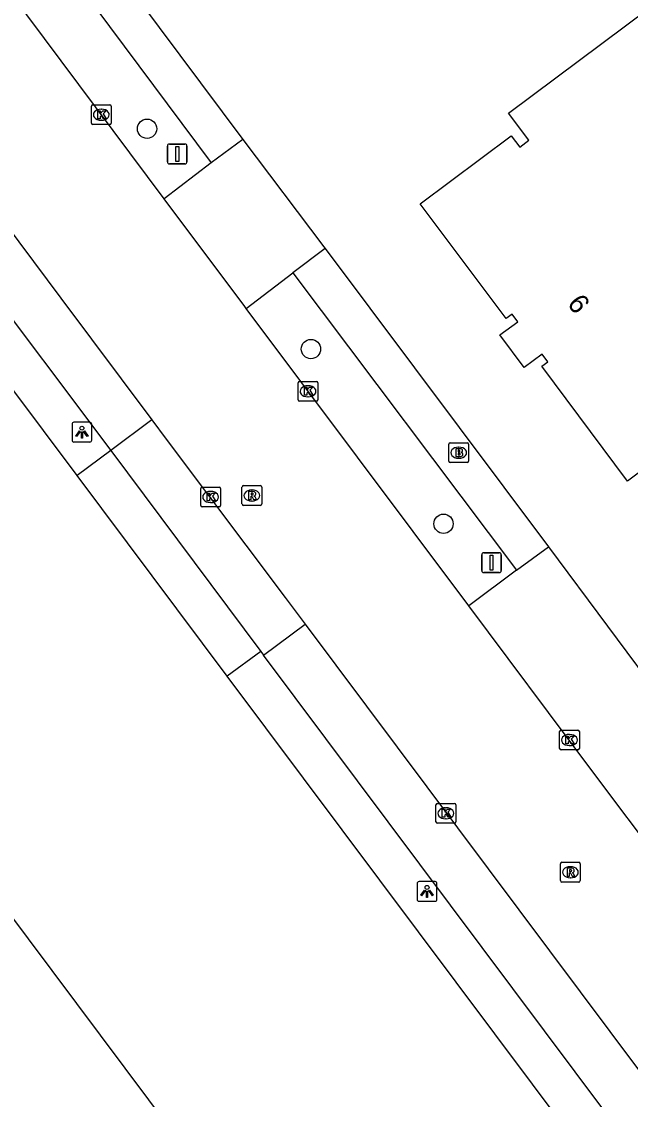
# Model space of a CAD drawing. Extents: x 156651 to 158072, y 387631 to 388990.
# Drawn here: x 157731.8 to 157762.6, y 388530.3 to 388584.8 of the extents above; entities that cross this region are included whole.
import ezdxf

# ---------------------------------------------------------------- set-up
doc = ezdxf.new("R2010")
doc.units = 0
for name, color, linetype in [('IMGEO_Boom', 7, 'Continuous'), ('IMGEO_Brandkraan', 7, 'Continuous'), ('IMGEO_Kolk', 7, 'Continuous'), ('IMGEO_Lichtpunt', 7, 'Continuous'), ('IMGEO_Pand', 7, 'Continuous'), ('IMGEO_Pand_nummerreeks', 7, 'Continuous'), ('IMGEO_Parkeervlak_open', 7, 'Continuous'), ('IMGEO_Rijbaan_lokaal_gesloten', 7, 'Continuous'), ('IMGEO_Rioolput', 7, 'Continuous'), ('IMGEO_Verkeersbordpaal', 7, 'Continuous'), ('IMGEO_Voetpad_open', 7, 'Continuous')]:
    doc.layers.add(name, color=color, linetype=linetype)

msp = doc.modelspace()

# ---------------------------------------------------------------- linework, layer by layer
at = {"layer": 'IMGEO_Boom'}
for centre in [(157738.13, 388579.359), (157746.416, 388568.217), (157753.12, 388559.377)]:
    msp.add_circle(centre, 0.489, dxfattribs=at)
at = {"layer": 'IMGEO_Brandkraan'}
for p, q in [((157753.387, 388562.548), (157753.387, 388563.4)), ((157753.462, 388563.474), (157754.314, 388563.474)), ((157753.875, 388563.254), (157753.9, 388563.254)), ((157754.388, 388563.4), (157754.388, 388562.548)), ((157753.898, 388562.694), (157753.873, 388562.694)), ((157754.314, 388562.474), (157753.462, 388562.474))]:
    msp.add_line(p, q, dxfattribs=at)
for points in [[(157753.387, 388562.548), (157753.387, 388563.4)], [(157753.462, 388563.474), (157754.314, 388563.474)], [(157754.388, 388563.4), (157754.388, 388562.548)], [(157753.735, 388563.174), (157753.735, 388562.774), (157753.948, 388562.774)], [(157753.966, 388563.174), (157753.735, 388563.174)], [(157753.914, 388563.093), (157753.86, 388563.093), (157753.86, 388563.017)], [(157753.86, 388563.017), (157753.913, 388563.017)], [(157753.922, 388562.941), (157753.86, 388562.941), (157753.86, 388562.86)], [(157753.86, 388562.86), (157753.922, 388562.86)], [(157754.314, 388562.474), (157753.462, 388562.474)]]:
    msp.add_lwpolyline(points, dxfattribs=at)
for centre, radius, start, end in [((157753.464, 388563.398), 0.0765, 91.552, 178.448), ((157753.464, 388563.398), 0.0765, 91.552, 178.448), ((157754.312, 388563.398), 0.0765, 1.552, 88.448), ((157754.312, 388563.398), 0.0765, 1.552, 88.448), ((157753.915, 388563.055), 0.0379, 267.8285, 90.9355), ((157753.923, 388562.9), 0.0404, 269.8759, 90.5077), ((157753.954, 388563.025), 0.251, 268.6676, 293.5347), ((157753.97, 388563.029), 0.145, 59.4692, 91.5367), ((157753.995, 388563.076), 0.0922, 285.5137, 58.1501), ((157754, 388562.884), 0.105, 301.3115, 78.989), ((157753.464, 388562.55), 0.0765, 181.552, 268.448), ((157753.464, 388562.55), 0.0765, 181.552, 268.448), ((157754.312, 388562.55), 0.0765, 271.552, 358.448), ((157754.312, 388562.55), 0.0765, 271.552, 358.448)]:
    msp.add_arc(centre, radius, start, end, dxfattribs=at)
for centre, major_axis, ratio, start_param, end_param in [((157753.874, 388562.974), (-0.387, 0.002), 0.722429, 4.712389, 7.853982), ((157753.899, 388562.974), (-0.39, 0.002), 0.717154, 1.570796, 4.712389)]:
    msp.add_ellipse(centre, major_axis=major_axis, ratio=ratio, start_param=start_param, end_param=end_param, dxfattribs=at)
at = {"layer": 'IMGEO_Kolk'}
for p, q in [((157735.316, 388579.642), (157735.316, 388580.494)), ((157735.391, 388580.568), (157736.243, 388580.568)), ((157735.804, 388580.348), (157735.829, 388580.348)), ((157736.317, 388580.494), (157736.317, 388579.642)), ((157735.827, 388579.788), (157735.802, 388579.788)), ((157736.243, 388579.568), (157735.391, 388579.568)), ((157745.767, 388565.654), (157745.767, 388566.506)), ((157745.842, 388566.58), (157746.694, 388566.58)), ((157746.768, 388566.506), (157746.768, 388565.654)), ((157746.255, 388566.36), (157746.28, 388566.36)), ((157746.694, 388565.58), (157745.842, 388565.58)), ((157746.278, 388565.8), (157746.253, 388565.8)), ((157740.843, 388560.307), (157740.843, 388561.159)), ((157740.918, 388561.233), (157741.77, 388561.233)), ((157741.844, 388561.159), (157741.844, 388560.307)), ((157741.331, 388561.013), (157741.356, 388561.013)), ((157741.77, 388560.233), (157740.918, 388560.233)), ((157741.354, 388560.453), (157741.329, 388560.453)), ((157758.987, 388548.015), (157758.987, 388548.867)), ((157759.062, 388548.941), (157759.914, 388548.941)), ((157759.475, 388548.721), (157759.5, 388548.721)), ((157759.988, 388548.867), (157759.988, 388548.015)), ((157759.498, 388548.161), (157759.473, 388548.161)), ((157759.914, 388547.941), (157759.062, 388547.941)), ((157752.814, 388545.234), (157753.666, 388545.234)), ((157752.739, 388544.308), (157752.739, 388545.16)), ((157753.227, 388545.014), (157753.252, 388545.014)), ((157753.74, 388545.16), (157753.74, 388544.308)), ((157753.666, 388544.234), (157752.814, 388544.234)), ((157753.25, 388544.454), (157753.225, 388544.454))]:
    msp.add_line(p, q, dxfattribs=at)
for points in [[(157735.316, 388579.642), (157735.316, 388580.494)], [(157735.391, 388580.568), (157736.243, 388580.568)], [(157735.637, 388580.268), (157735.76, 388580.268), (157735.76, 388580.117), (157735.89, 388580.268), (157736.054, 388580.268), (157735.908, 388580.117), (157736.061, 388579.868), (157735.909, 388579.868), (157735.824, 388580.032), (157735.76, 388579.965), (157735.76, 388579.868), (157735.637, 388579.868), (157735.637, 388580.268)], [(157736.317, 388580.494), (157736.317, 388579.642)], [(157736.243, 388579.568), (157735.391, 388579.568)], [(157745.767, 388565.654), (157745.767, 388566.506)], [(157745.842, 388566.58), (157746.694, 388566.58)], [(157746.768, 388566.506), (157746.768, 388565.654)], [(157746.088, 388566.28), (157746.211, 388566.28), (157746.211, 388566.129), (157746.341, 388566.28), (157746.505, 388566.28), (157746.359, 388566.129), (157746.512, 388565.88), (157746.36, 388565.88), (157746.275, 388566.044), (157746.211, 388565.977), (157746.211, 388565.88), (157746.088, 388565.88), (157746.088, 388566.28)], [(157746.694, 388565.58), (157745.842, 388565.58)], [(157740.843, 388560.307), (157740.843, 388561.159)], [(157740.918, 388561.233), (157741.77, 388561.233)], [(157741.844, 388561.159), (157741.844, 388560.307)], [(157741.164, 388560.933), (157741.287, 388560.933), (157741.287, 388560.782), (157741.417, 388560.933), (157741.581, 388560.933), (157741.435, 388560.782), (157741.588, 388560.533), (157741.436, 388560.533), (157741.351, 388560.697), (157741.287, 388560.63), (157741.287, 388560.533), (157741.164, 388560.533), (157741.164, 388560.933)], [(157741.77, 388560.233), (157740.918, 388560.233)], [(157758.987, 388548.015), (157758.987, 388548.867)], [(157759.062, 388548.941), (157759.914, 388548.941)], [(157759.308, 388548.641), (157759.431, 388548.641), (157759.431, 388548.49), (157759.561, 388548.641), (157759.725, 388548.641), (157759.579, 388548.49), (157759.732, 388548.241), (157759.58, 388548.241), (157759.495, 388548.405), (157759.431, 388548.338), (157759.431, 388548.241), (157759.308, 388548.241), (157759.308, 388548.641)], [(157759.988, 388548.867), (157759.988, 388548.015)], [(157759.914, 388547.941), (157759.062, 388547.941)], [(157752.814, 388545.234), (157753.666, 388545.234)], [(157752.739, 388544.308), (157752.739, 388545.16)], [(157753.06, 388544.934), (157753.183, 388544.934), (157753.183, 388544.783), (157753.313, 388544.934), (157753.477, 388544.934), (157753.331, 388544.783), (157753.484, 388544.534), (157753.332, 388544.534), (157753.247, 388544.698), (157753.183, 388544.631), (157753.183, 388544.534), (157753.06, 388544.534), (157753.06, 388544.934)], [(157753.74, 388545.16), (157753.74, 388544.308)], [(157753.666, 388544.234), (157752.814, 388544.234)]]:
    msp.add_lwpolyline(points, dxfattribs=at)
for centre, start, end in [((157735.393, 388580.492), 91.552, 178.448), ((157735.393, 388580.492), 91.552, 178.448), ((157736.241, 388580.492), 1.552, 88.448), ((157736.241, 388580.492), 1.552, 88.448), ((157735.393, 388579.644), 181.552, 268.448), ((157735.393, 388579.644), 181.552, 268.448), ((157736.241, 388579.644), 271.552, 358.448), ((157736.241, 388579.644), 271.552, 358.448), ((157745.844, 388566.504), 91.552, 178.448), ((157745.844, 388566.504), 91.552, 178.448), ((157746.692, 388566.504), 1.552, 88.448), ((157746.692, 388566.504), 1.552, 88.448), ((157745.844, 388565.656), 181.552, 268.448), ((157745.844, 388565.656), 181.552, 268.448), ((157746.692, 388565.656), 271.552, 358.448), ((157746.692, 388565.656), 271.552, 358.448), ((157740.92, 388561.157), 91.552, 178.448), ((157740.92, 388561.157), 91.552, 178.448), ((157741.768, 388561.157), 1.552, 88.448), ((157741.768, 388561.157), 1.552, 88.448), ((157740.92, 388560.309), 181.552, 268.448), ((157740.92, 388560.309), 181.552, 268.448), ((157741.768, 388560.309), 271.552, 358.448), ((157741.768, 388560.309), 271.552, 358.448), ((157759.064, 388548.865), 91.552, 178.448), ((157759.064, 388548.865), 91.552, 178.448), ((157759.912, 388548.865), 1.552, 88.448), ((157759.912, 388548.865), 1.552, 88.448), ((157759.064, 388548.017), 181.552, 268.448), ((157759.064, 388548.017), 181.552, 268.448), ((157759.912, 388548.017), 271.552, 358.448), ((157759.912, 388548.017), 271.552, 358.448), ((157752.816, 388545.158), 91.552, 178.448), ((157752.816, 388545.158), 91.552, 178.448), ((157753.664, 388545.158), 1.552, 88.448), ((157753.664, 388545.158), 1.552, 88.448), ((157752.816, 388544.31), 181.552, 268.448), ((157752.816, 388544.31), 181.552, 268.448), ((157753.664, 388544.31), 271.552, 358.448), ((157753.664, 388544.31), 271.552, 358.448)]:
    msp.add_arc(centre, 0.0765, start, end, dxfattribs=at)
for centre, major_axis, ratio, start_param, end_param in [((157735.803, 388580.068), (-0.387, 0.002), 0.722429, 4.712389, 7.853982), ((157735.828, 388580.068), (-0.39, 0.002), 0.717154, 1.570796, 4.712389), ((157746.254, 388566.08), (-0.387, 0.002), 0.722429, 4.712389, 7.853982), ((157746.279, 388566.08), (-0.39, 0.002), 0.717154, 1.570796, 4.712389), ((157741.33, 388560.733), (-0.387, 0.002), 0.722429, 4.712389, 7.853982), ((157741.355, 388560.733), (-0.39, 0.002), 0.717154, 1.570796, 4.712389), ((157759.474, 388548.441), (-0.387, 0.002), 0.722429, 4.712389, 7.853982), ((157759.499, 388548.441), (-0.39, 0.002), 0.717154, 1.570796, 4.712389), ((157753.226, 388544.734), (-0.387, 0.002), 0.722429, 4.712389, 7.853982), ((157753.251, 388544.734), (-0.39, 0.002), 0.717154, 1.570796, 4.712389)]:
    msp.add_ellipse(centre, major_axis=major_axis, ratio=ratio, start_param=start_param, end_param=end_param, dxfattribs=at)
at = {"layer": 'IMGEO_Lichtpunt'}
for p, q in [((157734.336, 388564.416), (157734.336, 388563.609)), ((157734.336, 388564.416), (157734.336, 388563.609)), ((157735.238, 388564.511), (157734.43, 388564.511)), ((157735.238, 388564.511), (157734.43, 388564.511)), ((157735.332, 388563.609), (157735.332, 388564.416)), ((157735.332, 388563.609), (157735.332, 388564.416)), ((157734.43, 388563.515), (157735.238, 388563.515)), ((157734.43, 388563.515), (157735.238, 388563.515)), ((157751.788, 388541.186), (157751.788, 388540.379)), ((157751.788, 388541.186), (157751.788, 388540.379)), ((157752.69, 388541.281), (157751.882, 388541.281)), ((157752.69, 388541.281), (157751.882, 388541.281)), ((157752.784, 388540.379), (157752.784, 388541.186)), ((157752.784, 388540.379), (157752.784, 388541.186)), ((157751.882, 388540.285), (157752.69, 388540.285)), ((157751.882, 388540.285), (157752.69, 388540.285))]:
    msp.add_line(p, q, dxfattribs=at)
for points in [[(157734.71, 388564.08), (157734.749, 388564.052), (157734.561, 388563.79), (157734.523, 388563.817), (157734.71, 388564.08)], [(157734.812, 388564.032), (157734.859, 388564.032), (157734.859, 388563.71), (157734.812, 388563.71), (157734.812, 388564.032)], [(157734.922, 388564.052), (157734.96, 388564.079), (157735.147, 388563.817), (157735.108, 388563.789), (157734.922, 388564.052)], [(157752.162, 388540.85), (157752.201, 388540.822), (157752.013, 388540.56), (157751.975, 388540.587), (157752.162, 388540.85)], [(157752.264, 388540.802), (157752.311, 388540.802), (157752.311, 388540.48), (157752.264, 388540.48), (157752.264, 388540.802)], [(157752.374, 388540.822), (157752.412, 388540.849), (157752.599, 388540.587), (157752.56, 388540.559), (157752.374, 388540.822)]]:
    msp.add_lwpolyline(points, dxfattribs=at)
for centre in [(157734.835, 388564.214), (157752.287, 388540.984)]:
    msp.add_circle(centre, 0.0994, dxfattribs=at)
for centre, start, end in [((157734.43, 388564.416), 90, 180), ((157734.43, 388564.416), 90, 180), ((157735.238, 388564.416), 0, 90), ((157735.238, 388564.416), 0, 90), ((157734.43, 388563.609), 180, 270), ((157734.43, 388563.609), 180, 270), ((157735.238, 388563.609), 270, 0), ((157735.238, 388563.609), 270, 360), ((157751.882, 388541.186), 90, 180), ((157751.882, 388541.186), 90, 180), ((157752.69, 388541.186), 0, 90), ((157752.69, 388541.186), 0, 90), ((157751.882, 388540.379), 180, 270), ((157751.882, 388540.379), 180, 270), ((157752.69, 388540.379), 270, 0), ((157752.69, 388540.379), 270, 360)]:
    msp.add_arc(centre, 0.0946, start, end, dxfattribs=at)
at = {"layer": 'IMGEO_Pand'}
for points in [[(157795.49, 388609.351), (157800.933, 388602.076), (157809.912, 388590.06), (157770.834, 388560.859), (157767.103, 388565.883), (157766.618, 388565.55), (157767.037, 388564.99), (157762.428, 388561.536), (157758.085, 388567.345), (157758.389, 388567.572), (157758.103, 388567.958), (157757.203, 388567.285), (157755.975, 388568.927), (157756.875, 388569.597), (157756.586, 388569.987), (157756.282, 388569.759), (157751.946, 388575.556), (157756.546, 388578.995), (157756.971, 388578.426), (157757.429, 388578.783), (157756.406, 388580.153), (157795.49, 388609.351)], [(157694.419, 388474.218), (157682.965, 388489.503), (157670.362, 388480.058), (157658.428, 388495.983), (157663.8, 388500), (157722.017, 388543.534), (157726.021, 388546.528), (157752.812, 388510.688), (157757.04, 388513.816), (157758.463, 388511.892), (157759.027, 388511.13), (157755.454, 388508.456), (157754.829, 388507.989), (157760.801, 388500), (157762.018, 388498.372), (157743.316, 388484.392), (157744.825, 388482.374)]]:
    msp.add_lwpolyline(points, dxfattribs=at)
at = {"layer": 'IMGEO_Parkeervlak_open'}
for points in [[(157738.371, 388564.633), (157736.304, 388563.087)], [(157744.014, 388552.734), (157746.116, 388554.3)]]:
    msp.add_lwpolyline(points, dxfattribs=at)
at = {"layer": 'IMGEO_Rijbaan_lokaal_gesloten'}
for points in [[(157677.044, 388646.782), (157678.366, 388644.971), (157691.031, 388628.022), (157702.886, 388612.138), (157715.525, 388595.248), (157733.77, 388570.785), (157738.371, 388564.633)], [(157739.001, 388575.812), (157729.45, 388588.589)], [(157743.149, 388570.269), (157743.08, 388570.36), (157739.001, 388575.812)], [(157754.398, 388555.23), (157743.149, 388570.269)], [(157738.371, 388564.633), (157739.101, 388563.658), (157745.11, 388555.645), (157746.116, 388554.3)], [(157764.445, 388541.799), (157760.423, 388547.176), (157754.398, 388555.23)], [(157746.116, 388554.3), (157786.233, 388500.645)]]:
    msp.add_lwpolyline(points, dxfattribs=at)
at = {"layer": 'IMGEO_Rioolput'}
for p, q in [((157742.93, 388560.382), (157742.93, 388561.234)), ((157743.005, 388561.308), (157743.857, 388561.308)), ((157743.418, 388561.088), (157743.443, 388561.088)), ((157743.931, 388561.234), (157743.931, 388560.382)), ((157743.441, 388560.528), (157743.416, 388560.528)), ((157743.857, 388560.308), (157743.005, 388560.308)), ((157759.034, 388541.327), (157759.034, 388542.179)), ((157759.109, 388542.253), (157759.961, 388542.253)), ((157759.522, 388542.033), (157759.547, 388542.033)), ((157760.035, 388542.179), (157760.035, 388541.327)), ((157759.545, 388541.473), (157759.52, 388541.473)), ((157759.961, 388541.253), (157759.109, 388541.253))]:
    msp.add_line(p, q, dxfattribs=at)
for points in [[(157742.93, 388560.382), (157742.93, 388561.234)], [(157743.005, 388561.308), (157743.857, 388561.308)], [(157743.931, 388561.234), (157743.931, 388560.382)], [(157743.519, 388561.006), (157743.267, 388561.008), (157743.267, 388560.608)], [(157743.267, 388560.608), (157743.391, 388560.608), (157743.391, 388560.77), (157743.402, 388560.77)], [(157743.445, 388560.927), (157743.391, 388560.927), (157743.391, 388560.846)], [(157743.391, 388560.846), (157743.443, 388560.846)], [(157743.449, 388560.741), (157743.52, 388560.608), (157743.66, 388560.608), (157743.595, 388560.734)], [(157743.857, 388560.308), (157743.005, 388560.308)], [(157759.034, 388541.327), (157759.034, 388542.179)], [(157759.109, 388542.253), (157759.961, 388542.253)], [(157760.035, 388542.179), (157760.035, 388541.327)], [(157759.623, 388541.951), (157759.371, 388541.953), (157759.371, 388541.553)], [(157759.371, 388541.553), (157759.495, 388541.553), (157759.495, 388541.715), (157759.506, 388541.715)], [(157759.549, 388541.872), (157759.495, 388541.872), (157759.495, 388541.791)], [(157759.495, 388541.791), (157759.547, 388541.791)], [(157759.553, 388541.686), (157759.624, 388541.553), (157759.764, 388541.553), (157759.699, 388541.679)], [(157759.961, 388541.253), (157759.109, 388541.253)]]:
    msp.add_lwpolyline(points, dxfattribs=at)
for centre, radius, start, end in [((157743.007, 388561.232), 0.0765, 91.552, 178.448), ((157743.007, 388561.232), 0.0765, 91.552, 178.448), ((157743.855, 388561.232), 0.0765, 1.552, 88.448), ((157743.855, 388561.232), 0.0765, 1.552, 88.448), ((157743.401, 388560.717), 0.0533, 26.0293, 88.6989), ((157743.427, 388561.035), 0.19, 274.7715, 282.9687), ((157743.451, 388560.831), 0.0964, 77.0061, 93.1865), ((157743.465, 388560.888), 0.0378, 276.6634, 79.6772), ((157743.518, 388560.896), 0.109, 350.3612, 89.416), ((157743.516, 388560.896), 0.112, 277.5842, 350.9817), ((157743.5, 388560.681), 0.108, 29.5134, 73.7905), ((157743.007, 388560.384), 0.0765, 181.552, 268.448), ((157743.007, 388560.384), 0.0765, 181.552, 268.448), ((157743.855, 388560.384), 0.0765, 271.552, 358.448), ((157743.855, 388560.384), 0.0765, 271.552, 358.448), ((157759.111, 388542.177), 0.0765, 91.552, 178.448), ((157759.111, 388542.177), 0.0765, 91.552, 178.448), ((157759.959, 388542.177), 0.0765, 1.552, 88.448), ((157759.959, 388542.177), 0.0765, 1.552, 88.448), ((157759.505, 388541.662), 0.0533, 26.0293, 88.6989), ((157759.531, 388541.98), 0.19, 274.7715, 282.9687), ((157759.555, 388541.776), 0.0964, 77.0061, 93.1865), ((157759.569, 388541.833), 0.0378, 276.6634, 79.6772), ((157759.622, 388541.841), 0.109, 350.3612, 89.416), ((157759.62, 388541.841), 0.112, 277.5842, 350.9817), ((157759.604, 388541.626), 0.108, 29.5134, 73.7905), ((157759.111, 388541.329), 0.0765, 181.552, 268.448), ((157759.111, 388541.329), 0.0765, 181.552, 268.448), ((157759.959, 388541.329), 0.0765, 271.552, 358.448), ((157759.959, 388541.329), 0.0765, 271.552, 358.448)]:
    msp.add_arc(centre, radius, start, end, dxfattribs=at)
for centre, major_axis, ratio, start_param, end_param in [((157743.417, 388560.808), (-0.387, 0.002), 0.722429, 4.712389, 7.853982), ((157743.442, 388560.808), (-0.39, 0.002), 0.717154, 1.570796, 4.712389), ((157759.521, 388541.753), (-0.387, 0.002), 0.722429, 4.712389, 7.853982), ((157759.546, 388541.753), (-0.39, 0.002), 0.717154, 1.570796, 4.712389)]:
    msp.add_ellipse(centre, major_axis=major_axis, ratio=ratio, start_param=start_param, end_param=end_param, dxfattribs=at)
at = {"layer": 'IMGEO_Verkeersbordpaal'}
for p, q in [((157739.258, 388578.585), (157740.048, 388578.585)), ((157740.048, 388578.585), (157739.258, 388578.585)), ((157739.158, 388577.685), (157739.158, 388578.485)), ((157739.158, 388578.485), (157739.158, 388577.685)), ((157740.148, 388578.485), (157740.148, 388577.685)), ((157740.148, 388577.685), (157740.148, 388578.485)), ((157740.048, 388577.585), (157739.258, 388577.585)), ((157739.258, 388577.585), (157740.048, 388577.585)), ((157755.051, 388557.01), (157755.051, 388557.81)), ((157755.051, 388557.81), (157755.051, 388557.01)), ((157755.151, 388557.91), (157755.941, 388557.91)), ((157755.941, 388557.91), (157755.151, 388557.91)), ((157756.041, 388557.81), (157756.041, 388557.01)), ((157756.041, 388557.01), (157756.041, 388557.81)), ((157755.941, 388556.91), (157755.151, 388556.91)), ((157755.151, 388556.91), (157755.941, 388556.91))]:
    msp.add_line(p, q, dxfattribs=at)
for points in [[(157739.578, 388578.46), (157739.728, 388578.46), (157739.728, 388577.71), (157739.578, 388577.71), (157739.578, 388578.46)], [(157755.471, 388557.785), (157755.621, 388557.785), (157755.621, 388557.035), (157755.471, 388557.035), (157755.471, 388557.785)]]:
    msp.add_lwpolyline(points, dxfattribs=at)
for centre, start, end in [((157739.258, 388578.485), 90, 180), ((157739.258, 388578.485), 90, 180), ((157740.048, 388578.485), 0, 90), ((157740.048, 388578.485), 360, 90), ((157739.258, 388577.685), 180, 270), ((157739.258, 388577.685), 180, 270), ((157740.048, 388577.685), 270, 0), ((157740.048, 388577.685), 270, 0), ((157755.151, 388557.81), 90, 180), ((157755.151, 388557.81), 90, 180), ((157755.941, 388557.81), 0, 90), ((157755.941, 388557.81), 360, 90), ((157755.151, 388557.01), 180, 270), ((157755.151, 388557.01), 180, 270), ((157755.941, 388557.01), 270, 0), ((157755.941, 388557.01), 270, 0)]:
    msp.add_arc(centre, 0.1, start, end, dxfattribs=at)
at = {"layer": 'IMGEO_Voetpad_open'}
for points in [[(157733.413, 388591.636), (157742.964, 388578.821)], [(157731.827, 388590.451), (157741.37, 388577.628)], [(157742.964, 388578.821), (157741.37, 388577.628)], [(157742.964, 388578.821), (157747.063, 388573.387), (157747.131, 388573.296)], [(157741.37, 388577.628), (157739.001, 388575.812)], [(157747.131, 388573.296), (157745.509, 388572.074)], [(157747.131, 388573.296), (157758.423, 388558.206)], [(157729.426, 388572.225), (157736.304, 388563.087)], [(157743.149, 388570.269), (157745.509, 388572.074)], [(157745.509, 388572.074), (157756.814, 388557.023)], [(157734.591, 388561.818), (157727.725, 388570.997)], [(157736.304, 388563.087), (157734.591, 388561.818)], [(157736.304, 388563.087), (157743.876, 388552.919)], [(157742.183, 388551.677), (157734.591, 388561.818)], [(157756.814, 388557.023), (157758.423, 388558.206)], [(157758.423, 388558.206), (157764.403, 388550.183), (157768.457, 388544.772)], [(157756.814, 388557.023), (157754.398, 388555.23)], [(157743.876, 388552.919), (157742.183, 388551.677)], [(157743.876, 388552.919), (157744.014, 388552.734)], [(157784.129, 388499.072), (157783.436, 388500), (157744.014, 388552.734)], [(157782.722, 388497.479), (157780.836, 388500), (157742.183, 388551.677)]]:
    msp.add_lwpolyline(points, dxfattribs=at)

# ---------------------------------------------------------------- texts
at = {"layer": 'IMGEO_Pand_nummerreeks'}
msp.add_text('6', height=1, rotation=306.8419, dxfattribs=at).set_placement((157759.341, 388570.509))

doc.saveas('drawing.dxf')
